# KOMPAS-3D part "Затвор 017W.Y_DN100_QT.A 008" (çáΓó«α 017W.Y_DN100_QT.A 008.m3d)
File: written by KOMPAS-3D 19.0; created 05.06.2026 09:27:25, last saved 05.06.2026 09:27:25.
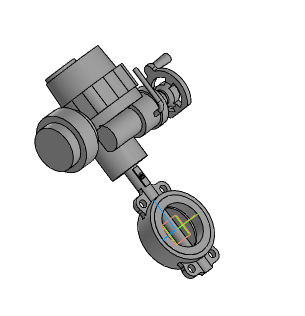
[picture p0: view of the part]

Document properties: Автор: Энергия; Полное имя файла: ..\..\..\3d для проектировщиков\x.x Тип 017W.Y(S) Затвор дисковый поворотный межфланцевый\Затвор 017W.Y(S)_DN32-DN1200_QT.A_MT903.A\Затвор 017W.Y_DN100_QT.A 008.a3d

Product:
- Part/product: Затвор 017W.Y_DN100_QT.A 008
    Масса: 42.3285

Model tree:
1. Операция без истории:1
